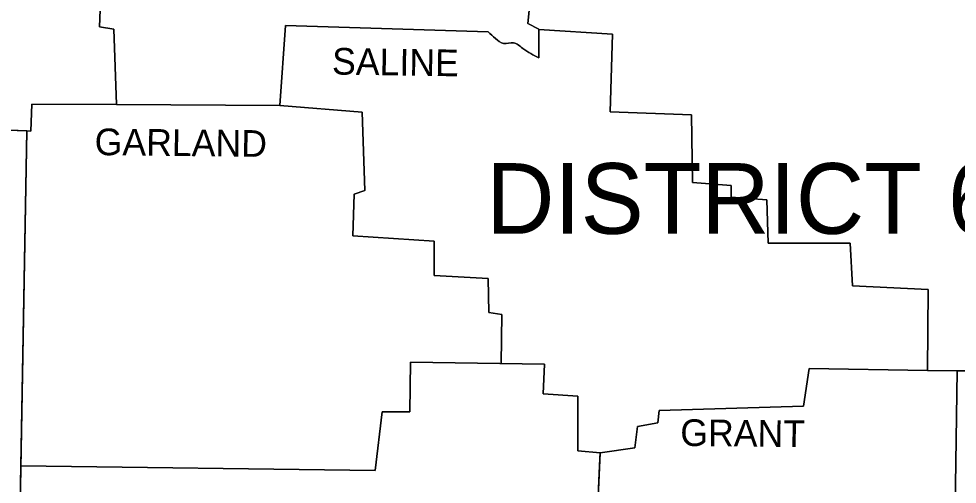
# Model space of a CAD drawing. Extents: x -28335 to 1228743, y -22428 to 152440.
# Drawn here: x 27629 to 31060, y 10013 to 11714 of the extents above; entities that cross this region are included whole.
import ezdxf

# ---------------------------------------------------------------- set-up
doc = ezdxf.new("R2010")
doc.units = 0
doc.layers.add('16', color=7, linetype='Continuous')
doc.layers.add('8', color=7, linetype='Continuous')

msp = doc.modelspace()

# ---------------------------------------------------------------- linework, layer by layer
at = {"layer": '16'}
for p, q in [((29530.6, 11674.5), (29530.6, 11571.6)), ((29530.6, 11674.5), (29800.2, 11657.6)), ((29800.2, 11657.6), (29791.1, 11374.5)), ((27677.6, 11401.7), (27673.9, 11303.7)), ((26771.5, 11338.2), (27659.5, 11304.3)), ((27659.5, 11304.3), (26771.5, 11338.2)), ((27659.5, 11304.3), (27636.8, 10081)), ((27659.5, 11304.3), (27673.9, 11303.7)), ((27673.9, 11303.7), (27659.5, 11304.3)), ((30092.4, 11116.2), (30232.8, 11104.9)), ((30232.8, 11104.9), (30232.8, 11061.9)), ((30232.8, 11061.9), (30364.2, 11052.8)), ((30364.2, 11052.8), (30368.8, 10894.2)), ((29347.1, 10640.5), (29394.7, 10633.7)), ((29394.7, 10633.7), (29392.3, 10454.7)), ((30950.9, 10429.4), (31059.7, 10427.6)), ((31059.7, 10427.6), (31560.2, 10429.6)), ((27636.8, 10081), (27633.1, 9881.7))]:
    msp.add_line(p, q, dxfattribs=at)
for points in [[(29530.6, 11571.6), (29530.6, 11675.8), (29489.8, 11696.1), (29505.7, 11854.7), (29784.3, 11870.6), (29793.4, 11958.9), (30090.1, 11970.2), (30083.3, 12031.4), (30088.4, 12030.8)], [(30246.4, 12013.3), (30088.4, 12030.8), (30083.3, 12031.4), (30090.1, 11970.2), (29793.4, 11958.9), (29784.3, 11870.6), (29505.7, 11854.7), (29489.8, 11696.1), (29530.6, 11675.8), (29530.6, 11674.5)], [(28067.2, 11861.5), (28019.6, 11847.9), (28008.3, 11786.8), (27972.1, 11789), (27960.7, 11757.3), (27926.8, 11746), (27924.5, 11684.8)], [(27986.1, 11400.1), (27976.6, 11675.8), (27924.5, 11684.8), (27926.8, 11746)], [(27924.5, 11684.8), (27976.6, 11675.8), (27986.1, 11400.1)], [(27986.1, 11400.1), (28583.7, 11397.1), (28604.1, 11689.4), (29344.8, 11666.7)], [(29344.8, 11666.7), (28604.1, 11689.4), (28583.7, 11397.1)], [(30950.9, 10429.4), (30953.2, 10724.4), (30676.8, 10737.9), (30667.8, 10894.2), (30368.8, 10894.2), (30364.2, 11052.8), (30232.8, 11061.9), (30232.8, 11104.9), (30092.4, 11116.2), (30087.9, 11363.2), (29791.1, 11374.5), (29800.2, 11657.6), (29530.6, 11674.5)], [(27673.9, 11303.7), (27677.6, 11401.7), (27986.1, 11400.1)], [(28583.7, 11397.1), (27986.1, 11400.1), (27677.6, 11401.7)], [(29392.3, 10454.7), (29394.7, 10633.7), (29347.1, 10640.5), (29344.8, 10765.1), (29147.8, 10776.5), (29147.8, 10901), (28851, 10921.4), (28855.5, 11073.2), (28894, 11086.8), (28885, 11372.2), (28583.7, 11397.1)], [(28583.7, 11397.1), (28885, 11372.2), (28894, 11086.8)], [(29791.1, 11374.5), (30087.9, 11363.2), (30092.4, 11116.2)], [(27633.1, 9881.7), (27636.8, 10081), (27659.5, 11304.3)], [(28894, 11086.8), (28855.5, 11073.2), (28851, 10921.4), (29147.8, 10901)], [(29147.8, 10901), (29147.8, 10776.5), (29344.8, 10765.1), (29347.1, 10640.5)], [(30368.8, 10894.2), (30667.8, 10894.2), (30676.8, 10737.9)], [(30676.8, 10737.9), (30953.2, 10724.4), (30950.9, 10429.4)], [(29754.9, 10128.6), (29673.3, 10135.4), (29673.3, 10334.7), (29546.5, 10343.8), (29551, 10452.5), (29061.7, 10459.3), (29059.4, 10278.1), (28957.5, 10278.1), (28932.6, 10062.9), (27636.8, 10081)], [(27636.8, 10081), (28932.6, 10062.9), (28957.5, 10278.1), (29059.4, 10278.1), (29061.7, 10459.3), (29392.3, 10454.7)], [(29392.3, 10454.7), (29551, 10452.5), (29546.5, 10343.8), (29673.3, 10334.7), (29673.3, 10135.4), (29754.9, 10128.6)], [(31059.7, 10427.6), (30950.9, 10429.4), (30518.3, 10436.7), (30497.9, 10298.5), (29970.1, 10282.6), (29965.5, 10237.3), (29890.8, 10223.7), (29881.7, 10146.7), (29754.9, 10128.6)], [(29754.9, 10128.6), (29881.7, 10146.7), (29890.8, 10223.7), (29965.5, 10237.3), (29970.1, 10282.6), (30497.9, 10298.5), (30518.3, 10436.7), (30950.9, 10429.4)], [(32496.6, 10433.2), (31560.2, 10429.6), (31059.7, 10427.6)], [(30987.2, 8937.1), (30994, 9505.7), (31046.1, 9507.9), (31059.7, 10427.6)], [(31059.7, 10427.6), (31046.1, 9507.9), (30994, 9505.7)], [(29754.9, 10128.6), (29753.9, 10107.9), (29727.7, 9535.1), (29707.3, 9541.9), (29709.5, 9236.4)], [(29707.3, 9541.9), (29727.7, 9535.1), (29753.9, 10107.9), (29754.9, 10128.6)], [(27636.8, 10081), (27636.8, 10081)]]:
    msp.add_lwpolyline(points, dxfattribs=at)
for points in [[(29344.8, 11666.7), (29372, 11641.8), (29401.5, 11623.7), (29437.7, 11625.9), (29471.7, 11605.5), (29530.6, 11571.6)], [(29530.6, 11571.6), (29471.7, 11605.5), (29437.7, 11625.9), (29401.5, 11623.7), (29372, 11641.8), (29344.8, 11666.7)]]:
    msp.add_spline(points, degree=3, dxfattribs=at)
at = {"layer": '8'}
msp.add_line((27659.5, 11304.3), (27633.1, 9881.7), dxfattribs=at)
for points in [[(30246.4, 12013.3), (30083.3, 12031.4), (30090.1, 11970.2), (29793.4, 11958.9), (29784.3, 11870.6), (29505.7, 11854.7), (29489.8, 11696.1), (29530.6, 11675.8), (29530.6, 11571.6)], [(27926.8, 11746), (27924.5, 11684.8), (27976.6, 11675.8), (27986.1, 11400.1)], [(29344.8, 11666.7), (28604.1, 11689.4), (28583.7, 11397.1), (27677.6, 11401.7), (27673.9, 11303.7)], [(29530.6, 11674.5), (29800.2, 11657.6), (29791.1, 11374.5), (30087.9, 11363.2), (30092.4, 11116.2), (30232.8, 11104.9), (30232.8, 11061.9), (30364.2, 11052.8), (30368.8, 10894.2), (30667.8, 10894.2), (30676.8, 10737.9), (30953.2, 10724.4), (30950.9, 10429.4)], [(28583.7, 11397.1), (28885, 11372.2), (28894, 11086.8), (28855.5, 11073.2), (28851, 10921.4), (29147.8, 10901), (29147.8, 10776.5), (29344.8, 10765.1), (29347.1, 10640.5), (29394.7, 10633.7), (29392.3, 10454.7)], [(27659.5, 11304.3), (26771.5, 11338.2)], [(27673.9, 11303.7), (27659.5, 11304.3)], [(27636.8, 10081), (28932.6, 10062.9), (28957.5, 10278.1), (29059.4, 10278.1), (29061.7, 10459.3), (29551, 10452.5), (29546.5, 10343.8), (29673.3, 10334.7), (29673.3, 10135.4), (29754.9, 10128.6), (29753.9, 10107.9)], [(29754.9, 10128.6), (29881.7, 10146.7), (29890.8, 10223.7), (29965.5, 10237.3), (29970.1, 10282.6), (30497.9, 10298.5), (30518.3, 10436.7), (31059.7, 10427.6)], [(31059.7, 10427.6), (31046.1, 9507.9), (30994, 9505.7), (30987.2, 8937.1)], [(29754.9, 10128.6), (29727.7, 9535.1), (29707.3, 9541.9), (29709.5, 9236.4)]]:
    msp.add_lwpolyline(points, dxfattribs=at)
msp.add_spline([(29530.6, 11571.6), (29471.7, 11605.5), (29437.7, 11625.9), (29401.5, 11623.7), (29372, 11641.8), (29344.8, 11666.7)], degree=3, dxfattribs=at)

# ---------------------------------------------------------------- texts
for s, rotation, p in [('SALINE', 359.1492, (28774, 11510.4)), ('GARLAND', 359.3658, (27906.4, 11215.9)), ('GRANT', 359.4032, (30047.1, 10153.5))]:
    msp.add_text(s, height=97.42, rotation=rotation, dxfattribs=at).set_placement(p)
msp.add_text('DISTRICT 6', height=258.24, dxfattribs=at).set_placement((29338, 10928.2))

doc.saveas('drawing.dxf')
